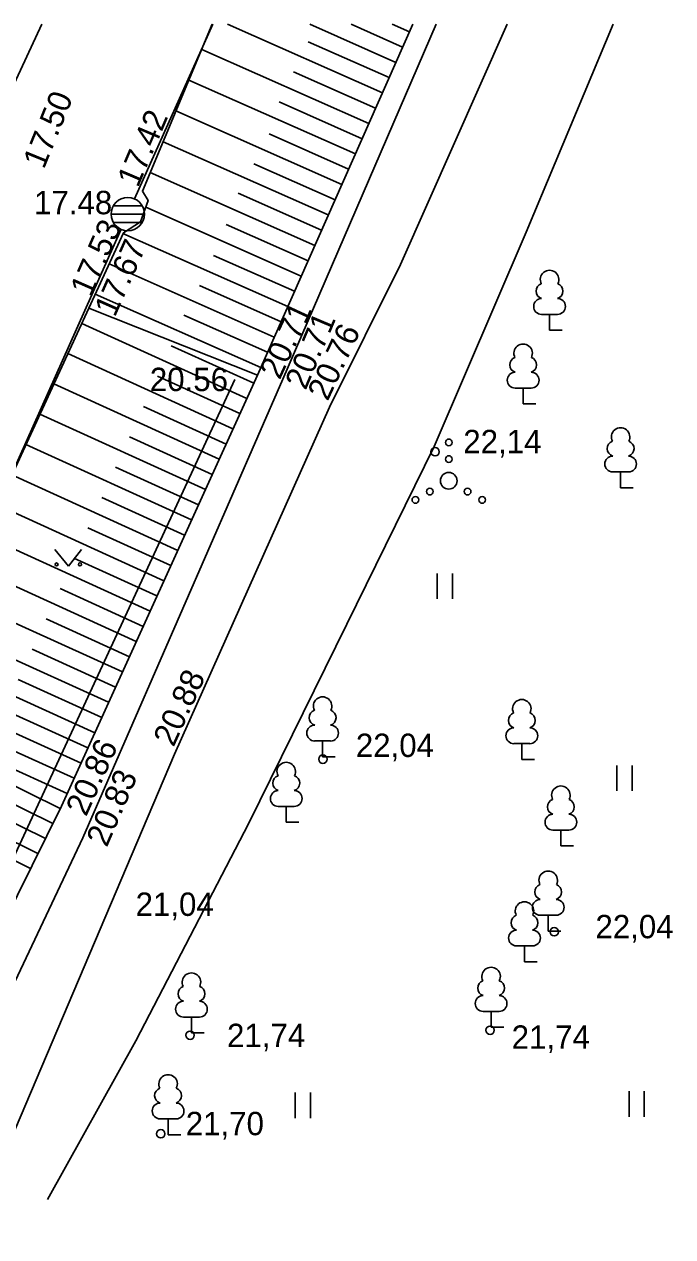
# Model space of a CAD drawing. Extents: x 714391 to 714584, y 6589993 to 6590151.
# Drawn here: x 714471.46 to 714490.89, y 6590114.75 to 6590151.08 of the extents above; entities that cross this region are included whole.
import ezdxf

# ---------------------------------------------------------------- set-up
doc = ezdxf.new("R2010")
doc.units = 0
for name, color, linetype in [('HALJASTUS', 7, 'Continuous'), ('KORGUS', 7, 'Continuous'), ('PUU', 7, 'Continuous'), ('RELJEEF', 7, 'Continuous'), ('SITRASS', 7, 'Continuous'), ('SKKAEV', 7, 'Continuous'), ('SKTRASS', 7, 'Continuous'), ('TEE', 7, 'Continuous')]:
    doc.layers.add(name, color=color, linetype=linetype)

msp = doc.modelspace()

# ---------------------------------------------------------------- linework, layer by layer
at = {"layer": 'HALJASTUS'}
for p, q in [((714466.315, 6590115.707), (714477.77, 6590140.433)), ((714472.377, 6590135.346), (714472.782, 6590134.841)), ((714472.782, 6590134.841), (714473.177, 6590135.346)), ((714483.832, 6590134.621), (714483.832, 6590133.859)), ((714484.288, 6590134.621), (714484.288, 6590133.859)), ((714489.222, 6590128.871), (714489.222, 6590128.109)), ((714489.678, 6590128.871), (714489.678, 6590128.109)), ((714479.582, 6590119.071), (714479.582, 6590118.309)), ((714480.038, 6590119.071), (714480.038, 6590118.309)), ((714489.582, 6590119.111), (714489.582, 6590118.349)), ((714490.038, 6590119.111), (714490.038, 6590118.349))]:
    msp.add_line(p, q, dxfattribs=at)
for centre, radius in [((714484.18, 6590138.55), 0.1), ((714484.18, 6590138.05), 0.1), ((714484.18, 6590137.4), 0.25), ((714483.615, 6590137.075), 0.1), ((714484.745, 6590137.075), 0.1), ((714483.18, 6590136.825), 0.1), ((714485.18, 6590136.825), 0.1), ((714472.429, 6590134.896), 0.0428), ((714473.129, 6590134.896), 0.0452)]:
    msp.add_circle(centre, radius, dxfattribs=at)
at = {"layer": 'KORGUS'}
for centre in [(714483.77, 6590138.27), (714480.41, 6590129.06), (714487.34, 6590123.89), (714485.42, 6590120.94), (714476.43, 6590120.79), (714475.55, 6590117.84)]:
    msp.add_circle(centre, 0.125, dxfattribs=at)
at = {"layer": 'PUU'}
for p, q in [((714487.44, 6590142.385), (714486.96, 6590142.385)), ((714487.2, 6590141.91), (714487.2, 6590142.385)), ((714487.58, 6590141.91), (714487.2, 6590141.91)), ((714486.65, 6590140.175), (714486.17, 6590140.175)), ((714486.41, 6590139.7), (714486.41, 6590140.175)), ((714486.79, 6590139.7), (714486.41, 6590139.7)), ((714489.57, 6590137.665), (714489.09, 6590137.665)), ((714489.33, 6590137.19), (714489.33, 6590137.665)), ((714489.71, 6590137.19), (714489.33, 6590137.19)), ((714480.64, 6590129.605), (714480.16, 6590129.605)), ((714480.4, 6590129.13), (714480.4, 6590129.605)), ((714486.61, 6590129.525), (714486.13, 6590129.525)), ((714486.37, 6590129.05), (714486.37, 6590129.525)), ((714480.78, 6590129.13), (714480.4, 6590129.13)), ((714486.75, 6590129.05), (714486.37, 6590129.05)), ((714479.55, 6590127.645), (714479.07, 6590127.645)), ((714479.31, 6590127.17), (714479.31, 6590127.645)), ((714479.69, 6590127.17), (714479.31, 6590127.17)), ((714487.78, 6590126.935), (714487.3, 6590126.935)), ((714487.54, 6590126.46), (714487.54, 6590126.935)), ((714487.92, 6590126.46), (714487.54, 6590126.46)), ((714487.4, 6590124.385), (714486.92, 6590124.385)), ((714487.16, 6590123.91), (714487.16, 6590124.385)), ((714487.54, 6590123.91), (714487.16, 6590123.91)), ((714486.69, 6590123.465), (714486.21, 6590123.465)), ((714486.45, 6590122.99), (714486.45, 6590123.465)), ((714486.83, 6590122.99), (714486.45, 6590122.99)), ((714485.69, 6590121.505), (714485.21, 6590121.505)), ((714485.45, 6590121.03), (714485.45, 6590121.505)), ((714476.71, 6590121.335), (714476.23, 6590121.335)), ((714476.47, 6590120.86), (714476.47, 6590121.335)), ((714485.83, 6590121.03), (714485.45, 6590121.03)), ((714476.85, 6590120.86), (714476.47, 6590120.86)), ((714476.01, 6590118.285), (714475.53, 6590118.285)), ((714475.77, 6590117.81), (714475.77, 6590118.285)), ((714476.15, 6590117.81), (714475.77, 6590117.81))]:
    msp.add_line(p, q, dxfattribs=at)
for centre, radius, start, end in [((714487.2, 6590143.43), 0.277, 332.5799, 207.4201), ((714487.03, 6590143.083), 0.233, 109.0217, 253.1415), ((714487.37, 6590143.083), 0.233, 286.8508, 70.9859), ((714486.963, 6590142.622), 0.238, 90.0016, 269.3953), ((714487.437, 6590142.622), 0.238, 270.6047, 89.9984), ((714486.41, 6590141.22), 0.277, 332.5799, 207.4201), ((714486.24, 6590140.873), 0.233, 109.0217, 253.1415), ((714486.58, 6590140.873), 0.233, 286.8508, 70.9859), ((714486.173, 6590140.412), 0.238, 90.0016, 269.3953), ((714486.647, 6590140.412), 0.238, 270.6047, 89.9984), ((714489.33, 6590138.71), 0.277, 332.5799, 207.4201), ((714489.16, 6590138.363), 0.233, 109.0217, 253.1415), ((714489.5, 6590138.363), 0.233, 286.8508, 70.9859), ((714489.093, 6590137.902), 0.238, 90.0016, 269.3953), ((714489.567, 6590137.902), 0.238, 270.6047, 89.9984), ((714480.4, 6590130.65), 0.277, 332.5799, 207.4201), ((714486.37, 6590130.57), 0.277, 332.5799, 207.4201), ((714480.23, 6590130.303), 0.233, 109.0217, 253.1415), ((714480.57, 6590130.303), 0.233, 286.8508, 70.9859), ((714480.163, 6590129.842), 0.238, 90.0016, 269.3953), ((714480.637, 6590129.842), 0.238, 270.6047, 89.9984), ((714486.2, 6590130.223), 0.233, 109.0217, 253.1415), ((714486.54, 6590130.223), 0.233, 286.8508, 70.9859), ((714486.133, 6590129.762), 0.238, 90.0016, 269.3953), ((714486.607, 6590129.762), 0.238, 270.6047, 89.9984), ((714479.31, 6590128.69), 0.277, 332.5799, 207.4201), ((714479.14, 6590128.343), 0.233, 109.0217, 253.1415), ((714479.48, 6590128.343), 0.233, 286.8508, 70.9859), ((714479.073, 6590127.882), 0.238, 90.0016, 269.3953), ((714479.547, 6590127.882), 0.238, 270.6047, 89.9984), ((714487.54, 6590127.98), 0.277, 332.5799, 207.4201), ((714487.37, 6590127.633), 0.233, 109.0217, 253.1415), ((714487.71, 6590127.633), 0.233, 286.8508, 70.9859), ((714487.303, 6590127.172), 0.238, 90.0016, 269.3953), ((714487.777, 6590127.172), 0.238, 270.6047, 89.9984), ((714487.16, 6590125.43), 0.277, 332.5799, 207.4201), ((714486.99, 6590125.083), 0.233, 109.0217, 253.1415), ((714487.33, 6590125.083), 0.233, 286.8508, 70.9859), ((714486.45, 6590124.51), 0.277, 332.5799, 207.4201), ((714486.923, 6590124.622), 0.238, 90.0016, 269.3953), ((714487.397, 6590124.622), 0.238, 270.6047, 89.9984), ((714486.28, 6590124.163), 0.233, 109.0217, 253.1415), ((714486.62, 6590124.163), 0.233, 286.8508, 70.9859), ((714486.213, 6590123.702), 0.238, 90.0016, 269.3953), ((714486.687, 6590123.702), 0.238, 270.6047, 89.9984), ((714485.45, 6590122.55), 0.277, 332.5799, 207.4201), ((714476.47, 6590122.38), 0.277, 332.5799, 207.4201), ((714476.3, 6590122.033), 0.233, 109.0217, 253.1415), ((714476.64, 6590122.033), 0.233, 286.8508, 70.9859), ((714485.28, 6590122.203), 0.233, 109.0217, 253.1415), ((714485.62, 6590122.203), 0.233, 286.8508, 70.9859), ((714476.233, 6590121.572), 0.238, 90.0016, 269.3953), ((714476.707, 6590121.572), 0.238, 270.6047, 89.9984), ((714485.213, 6590121.742), 0.238, 90.0016, 269.3953), ((714485.687, 6590121.742), 0.238, 270.6047, 89.9984), ((714475.77, 6590119.33), 0.277, 332.5799, 207.4201), ((714475.6, 6590118.983), 0.233, 109.0217, 253.1415), ((714475.94, 6590118.983), 0.233, 286.8508, 70.9859), ((714475.533, 6590118.522), 0.238, 90.0016, 269.3953), ((714476.007, 6590118.522), 0.238, 270.6047, 89.9984)]:
    msp.add_arc(centre, radius, start, end, dxfattribs=at)
at = {"layer": 'RELJEEF'}
for p, q in [((714482.19, 6590149.02), (714477.548, 6590151.075)), ((714482.595, 6590149.934), (714480.018, 6590151.075)), ((714482.798, 6590150.391), (714481.253, 6590151.075)), ((714483, 6590150.848), (714482.488, 6590151.075)), ((714482.393, 6590149.477), (714479.965, 6590150.552)), ((714481.786, 6590148.105), (714476.779, 6590150.323)), ((714481.381, 6590147.191), (714476.392, 6590149.4)), ((714481.988, 6590148.563), (714479.529, 6590149.651)), ((714481.583, 6590147.648), (714479.096, 6590148.75)), ((714480.976, 6590146.277), (714476.006, 6590148.478)), ((714480.571, 6590145.362), (714475.619, 6590147.555)), ((714481.178, 6590146.734), (714478.794, 6590147.79)), ((714480.773, 6590145.82), (714478.343, 6590146.896)), ((714480.166, 6590144.448), (714475.232, 6590146.633)), ((714480.368, 6590144.905), (714477.87, 6590146.012)), ((714479.761, 6590143.534), (714475.1, 6590145.598)), ((714479.963, 6590143.991), (714477.512, 6590145.076)), ((714479.356, 6590142.619), (714474.409, 6590144.81)), ((714478.951, 6590141.705), (714474.006, 6590143.895)), ((714479.559, 6590143.076), (714477.132, 6590144.151)), ((714479.154, 6590142.162), (714476.706, 6590143.246)), ((714478.546, 6590140.791), (714473.587, 6590142.987)), ((714473.184, 6590142.116), (714478.129, 6590139.866)), ((714478.749, 6590141.248), (714476.238, 6590142.36)), ((714475.865, 6590141.445), (714478.336, 6590140.321)), ((714472.765, 6590141.208), (714477.714, 6590138.956)), ((714472.345, 6590140.3), (714477.3, 6590138.046)), ((714475.448, 6590140.536), (714477.921, 6590139.411)), ((714475.031, 6590139.627), (714477.507, 6590138.501)), ((714471.926, 6590139.392), (714476.886, 6590137.136)), ((714471.507, 6590138.484), (714476.472, 6590136.225)), ((714474.614, 6590138.718), (714477.093, 6590137.591)), ((714474.198, 6590137.809), (714476.679, 6590136.68)), ((714471.087, 6590137.576), (714476.058, 6590135.315)), ((714470.668, 6590136.669), (714475.644, 6590134.405)), ((714473.781, 6590136.9), (714476.265, 6590135.77)), ((714473.364, 6590135.991), (714475.851, 6590134.86)), ((714470.248, 6590135.761), (714475.23, 6590133.495)), ((714469.829, 6590134.853), (714474.816, 6590132.584)), ((714472.948, 6590135.082), (714475.437, 6590133.95)), ((714472.531, 6590134.173), (714475.023, 6590133.039)), ((714469.41, 6590133.945), (714474.402, 6590131.674)), ((714468.99, 6590133.037), (714473.988, 6590130.764)), ((714472.114, 6590133.264), (714474.609, 6590132.129)), ((714471.697, 6590132.355), (714474.195, 6590131.219)), ((714468.581, 6590132.125), (714473.574, 6590129.854)), ((714468.184, 6590131.207), (714473.16, 6590128.943)), ((714471.281, 6590131.446), (714473.781, 6590130.309)), ((714470.874, 6590130.532), (714473.367, 6590129.398)), ((714467.787, 6590130.289), (714472.746, 6590128.033)), ((714467.46, 6590129.534), (714472.314, 6590127.131)), ((714470.469, 6590129.618), (714472.953, 6590128.488)), ((714470.098, 6590128.786), (714472.536, 6590127.579)), ((714467.063, 6590128.615), (714471.871, 6590126.235)), ((714469.677, 6590127.879), (714472.092, 6590126.683)), ((714469.256, 6590126.971), (714471.649, 6590125.787))]:
    msp.add_line(p, q, dxfattribs=at)
for points in [[(714489.103, 6590151.075), (714486.5, 6590144.85), (714483.74, 6590138.43), (714481.13, 6590133.1), (714478.19, 6590127.14), (714474.8, 6590120.62), (714472.156, 6590115.873)], [(714478.445, 6590140.562), (714483.101, 6590151.075)], [(714458.683, 6590107.808), (714459.134, 6590108.095), (714463.55, 6590110.904), (714465.985, 6590114.345), (714472.574, 6590127.656), (714478.445, 6590140.562)]]:
    msp.add_lwpolyline(points, dxfattribs=at)
at = {"layer": 'SITRASS'}
msp.add_line((714445.318, 6590093.669), (714471.983, 6590151.075), dxfattribs=at)
at = {"layer": 'SKKAEV'}
for p, q in [((714474.063, 6590145.388), (714475.063, 6590145.388)), ((714474.993, 6590145.638), (714474.133, 6590145.638)), ((714474.993, 6590145.138), (714474.133, 6590145.138))]:
    msp.add_line(p, q, dxfattribs=at)
msp.add_circle((714474.563, 6590145.388), 0.5, dxfattribs=at)
at = {"layer": 'SKTRASS'}
for p, q in [((714474.767, 6590145.844), (714477.106, 6590151.075)), ((714458.254, 6590108.91), (714474.359, 6590144.932))]:
    msp.add_line(p, q, dxfattribs=at)
at = {"layer": 'TEE'}
msp.add_line((714478.445, 6590140.562), (714473.396, 6590142.574), dxfattribs=at)
for points in [[(714583.92, 6590101.143), (714565.419, 6590101.225), (714549.748, 6590101.3), (714530.696, 6590101.382), (714516.957, 6590101.382), (714497.906, 6590101.442), (714488.527, 6590101.467), (714476.238, 6590101.479), (714465.964, 6590101.492), (714465.149, 6590101.593), (714461.989, 6590102.308), (714461.271, 6590102.628), (714460.534, 6590103.105), (714459.97, 6590103.737), (714459.406, 6590104.596), (714458.782, 6590106.528), (714458.59, 6590109.02), (714468.756, 6590132.53), (714474.437, 6590144.828), (714474.939, 6590145.152), (714475.17, 6590145.792), (714474.999, 6590146.077), (714477.095, 6590151.075)], [(714483.807, 6590151.075), (714479.211, 6590140.446), (714473.212, 6590126.702), (714468.119, 6590115.935), (714463.556, 6590104.916), (714462.138, 6590102.626), (714461.947, 6590102.318)], [(714485.932, 6590151.075), (714482.73, 6590143.88), (714480.61, 6590139.609), (714475.962, 6590129.206), (714470.061, 6590115.343), (714465.263, 6590104.4), (714464.405, 6590102.057), (714464.305, 6590101.784)]]:
    msp.add_lwpolyline(points, dxfattribs=at)

# ---------------------------------------------------------------- texts
at = {"layer": 'KORGUS'}
for s, rotation, p in [('17.50', 67.818, (714472.048, 6590146.712)), ('17.42', 66.8937, (714474.863, 6590146.158)), ('17.53', 66.2838, (714473.451, 6590142.878)), ('17.67', 65.996, (714474.173, 6590142.276)), ('20.71', 65.1363, (714479.116, 6590140.402)), ('20.71', 66.9948, (714479.892, 6590140.09)), ('20.76', 64.8781, (714480.552, 6590139.762)), ('20.88', 65.6097, (714475.935, 6590129.401)), ('20.86', 65.709, (714473.314, 6590127.317)), ('20.83', 66.5713, (714473.934, 6590126.398))]:
    msp.add_text(s, height=0.7, rotation=rotation, dxfattribs=at).set_placement(p)
for s, p in [('17.48', (714471.753, 6590145.384)), ('20.56', (714475.223, 6590140.086)), ('22,14', (714484.616, 6590138.225)), ('22,04', (714481.396, 6590129.125)), ('21,04', (714474.796, 6590124.365)), ('22,04', (714488.576, 6590123.695)), ('21,74', (714477.536, 6590120.435)), ('21,74', (714486.066, 6590120.385)), ('21,70', (714476.299, 6590117.795))]:
    msp.add_text(s, height=0.7, dxfattribs=at).set_placement(p)

doc.saveas('drawing.dxf')
